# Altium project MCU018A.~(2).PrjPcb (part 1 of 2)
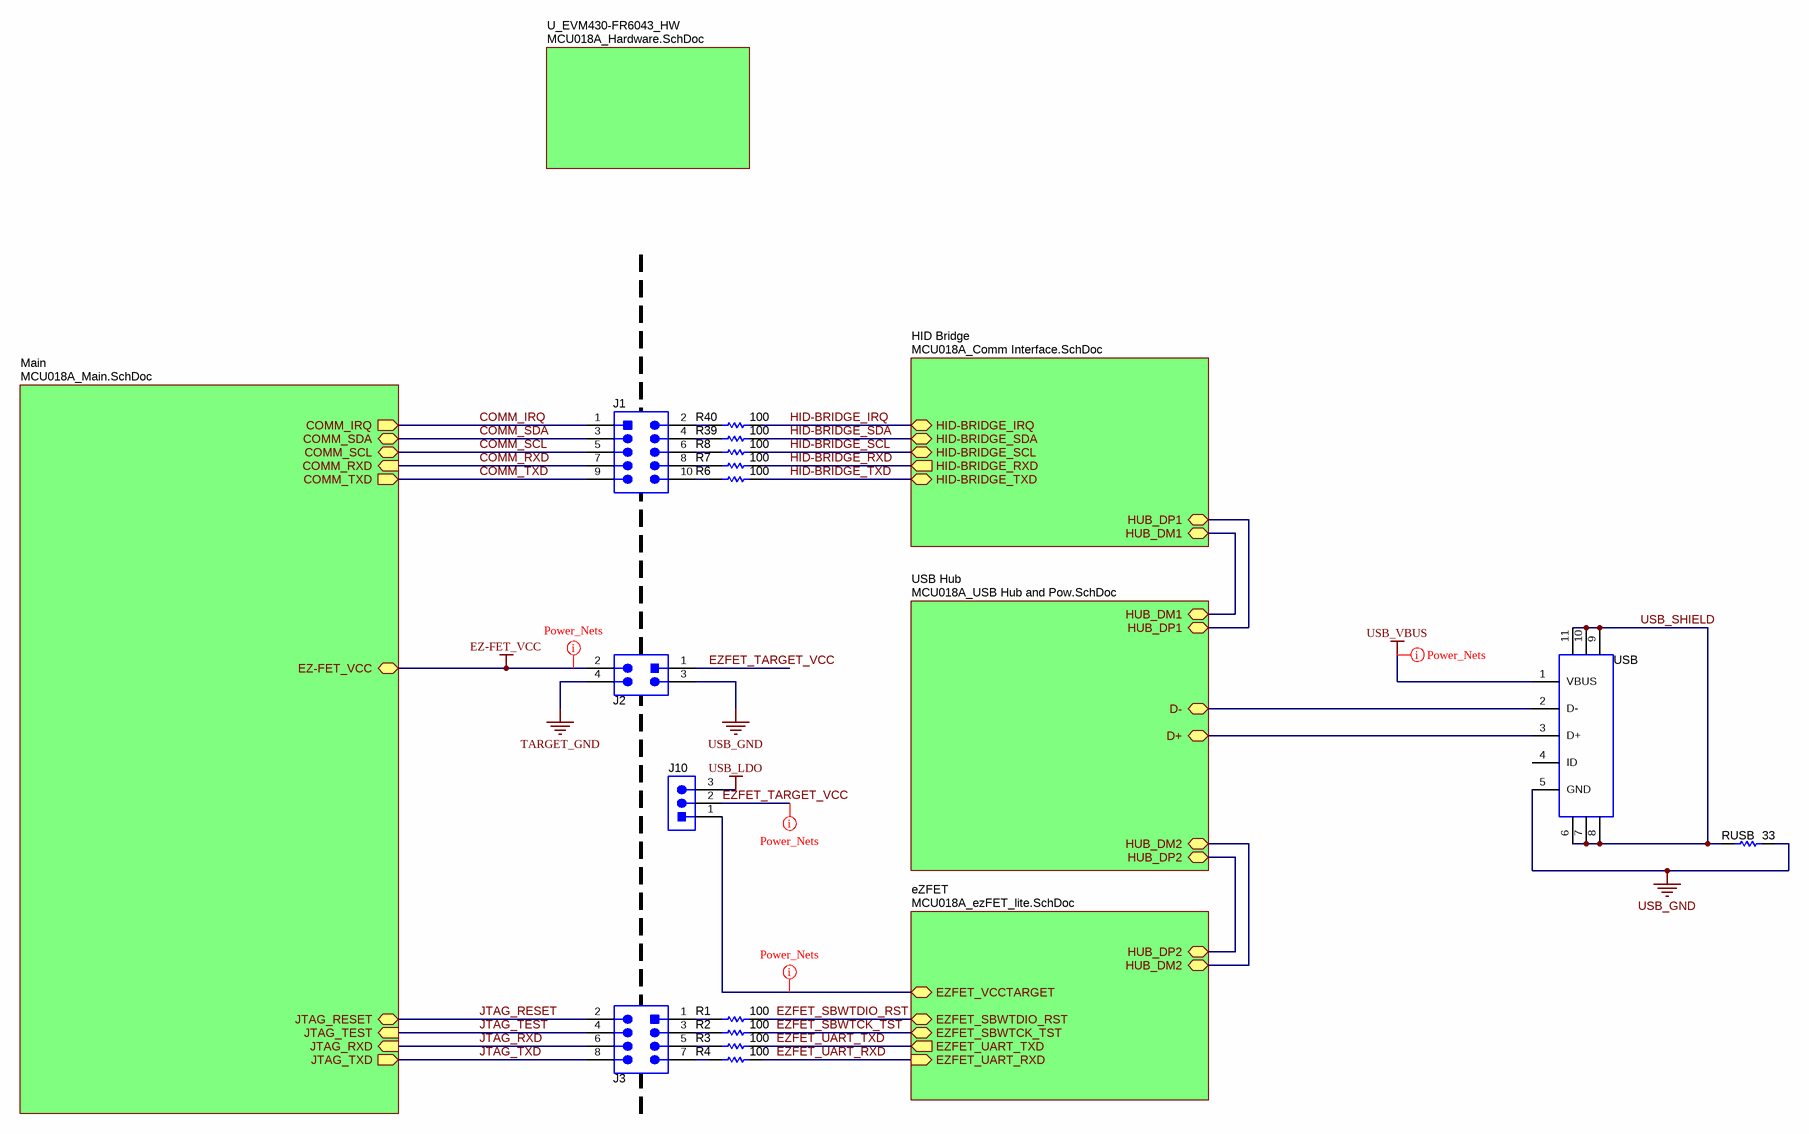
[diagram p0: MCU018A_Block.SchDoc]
TechSupport: http://www.ti.com/support; SCH_Rev: A; PRJ_Title: EVM430-FR6047; PRJ_Number: MCU018; PRJ_Engineer: Eddie LaCost; PRJ_Customer: Public Release; PCB_Rev: A; PCB_Layout: Eddie LaCost; Orderable: EVM430-FR6047; CopyrightYear: 2016
6 sheets, 270 parts. Net scope: hierarchical (ports join the sheet entries above them; power ports are global).
Board file: MCU018A.PcbDoc
Sheets:
  MCU018A_Block.SchDoc
    USB Hub = MCU018A_USB Hub and Pow.SchDoc
    U_EVM430-FR6043_HW = MCU018A_Hardware.SchDoc
    HID Bridge = MCU018A_Comm Interface.SchDoc
    eZFET = MCU018A_ezFET_lite.SchDoc
    Main = MCU018A_Main.SchDoc

## Sheet MCU018A_Block.SchDoc
size 431 x 279 mm; Date: Not shown in title block; ApprovedBy: Not shown in title block; CheckedBy: Not shown in title block; Author: Not shown in title block; CompanyName: Not shown in title block; Engineer: Not shown in title block; Organization: Not shown in title block; Address1: Not shown in title block; Address2: Not shown in title block; Address3: Not shown in title block; Address4: Not shown in title block; DocumentNumber: 1; Revision: Use project parameter SCH_Rev; SheetNumber: 1; SheetTotal: 6; PageSetup: Record=PageOptions¦CenterHorizontal=True¦CenterVertical=True¦PrintScale=1.00¦XCorrection=1.00¦YCorrection=1.00¦PrintKind=0¦BorderSize=5000000¦LeftOffset=0¦BottomOffset=0¦Orientation=2¦PaperLength=1000¦PaperWidth=1000¦Scale=100¦PaperSource=15¦PrintQuality=600¦MediaType=1¦DitherType=10¦PaperKind=Letter¦PrintScaleMode=1

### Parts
J1  61301021121  [WURTH_61301021121]  (value not drawn)
J2  PBC02DAAN  [Sullins_PxC02DAAN]  (value not drawn)
J3  PEC04DAAN  [CONN_PEC04DAAN]  (value not drawn)
J10  61300311121  [WURTH_61300311121]  (value not drawn)
R1  ValueDisplayed: 100  [0402S]  (hidden comment: CRCW0402100RJNED)
R2  ValueDisplayed: 100  [0402S]  (hidden comment: CRCW0402100RJNED)
R3  ValueDisplayed: 100  [0402S]  (hidden comment: CRCW0402100RJNED)
R4  ValueDisplayed: 100  [0402S]  (hidden comment: CRCW0402100RJNED)
R6  ValueDisplayed: 100  [0402S]  (hidden comment: CRCW0402100RJNED)
R7  ValueDisplayed: 100  [0402S]  (hidden comment: CRCW0402100RJNED)
R8  ValueDisplayed: 100  [0402S]  (hidden comment: CRCW0402100RJNED)
R39  ValueDisplayed: 100  [0402S]  (hidden comment: CRCW0402100RJNED)
R40  ValueDisplayed: 100  [0402S]  (hidden comment: CRCW0402100RJNED)
RUSB  value 33  [0402S]  (hidden comment: CRCW040233R0JNED)
USB  1051640001  [Molex_1051640001]  (value not drawn)

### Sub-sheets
eZFET = MCU018A_ezFET_lite.SchDoc: EZFET_VCCTARGET, EZFET_SBWTDIO_RST, EZFET_SBWTCK_TST, EZFET_UART_TXD, EZFET_UART_RXD, HUB_DP2, HUB_DM2
HID Bridge = MCU018A_Comm Interface.SchDoc: HID-BRIDGE_TXD, HID-BRIDGE_RXD, HID-BRIDGE_SCL, HID-BRIDGE_SDA, HID-BRIDGE_IRQ, HUB_DM1, HUB_DP1
Main = MCU018A_Main.SchDoc: COMM_IRQ, COMM_SDA, COMM_SCL, COMM_RXD, COMM_TXD, EZ-FET_VCC, JTAG_RESET, JTAG_TEST, JTAG_RXD, JTAG_TXD
U_EVM430-FR6043_HW = MCU018A_Hardware.SchDoc: no entries
USB Hub = MCU018A_USB Hub and Pow.SchDoc: HUB_DM1, HUB_DP1, D-, D+, HUB_DM2, HUB_DP2

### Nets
EZ-FET_VCC: J2.2 ; sheet Main/EZ-FET_VCC  [project net EZFET_VCC]
TARGET_GND: J2.4
USB_GND: J2.3 RUSB.1 USB.5(GND)
USB_LDO: J10.3
USB_VBUS: USB.1(VBUS)
COMM_IRQ: J1.1 ; sheet Main/COMM_IRQ
COMM_RXD: J1.7 ; sheet Main/COMM_RXD
COMM_SCL: J1.5 ; sheet Main/COMM_SCL
COMM_SDA: J1.3 ; sheet Main/COMM_SDA
COMM_TXD: J1.9 ; sheet Main/COMM_TXD
D+: USB.3(D+) ; sheet USB Hub/D+
D-: USB.2(D-) ; sheet USB Hub/D-
EZFET_SBWTCK_TST: R2.1 ; sheet eZFET/EZFET_SBWTCK_TST
EZFET_SBWTDIO_RST: R1.1 ; sheet eZFET/EZFET_SBWTDIO_RST
EZFET_TARGET_VCC: J2.1 J10.2
EZFET_UART_RXD: R4.1 ; sheet eZFET/EZFET_UART_RXD
EZFET_UART_TXD: R3.1 ; sheet eZFET/EZFET_UART_TXD
EZFET_VCCTARGET: J10.1 ; sheet eZFET/EZFET_VCCTARGET
HID-BRIDGE_IRQ: R40.1 ; sheet HID Bridge/HID-BRIDGE_IRQ
HID-BRIDGE_RXD: R7.1 ; sheet HID Bridge/HID-BRIDGE_RXD
HID-BRIDGE_SCL: R8.1 ; sheet HID Bridge/HID-BRIDGE_SCL
HID-BRIDGE_SDA: R39.1 ; sheet HID Bridge/HID-BRIDGE_SDA
HID-BRIDGE_TXD: R6.1 ; sheet HID Bridge/HID-BRIDGE_TXD
HUB_DM1: sheet USB Hub/HUB_DM1, sheet HID Bridge/HUB_DM1
HUB_DM2: sheet USB Hub/HUB_DM2, sheet eZFET/HUB_DM2
HUB_DP1: sheet USB Hub/HUB_DP1, sheet HID Bridge/HUB_DP1
HUB_DP2: sheet USB Hub/HUB_DP2, sheet eZFET/HUB_DP2
JTAG_RESET: J3.2 ; sheet Main/JTAG_RESET
JTAG_RXD: J3.6 ; sheet Main/JTAG_RXD
JTAG_TEST: J3.4 ; sheet Main/JTAG_TEST
JTAG_TXD: J3.8 ; sheet Main/JTAG_TXD
USB_SHIELD: RUSB.2 USB.6 USB.7 USB.8 USB.9 USB.10 USB.11
NetJ1_2: J1.2 R40.2
NetJ1_4: J1.4 R39.2
NetJ1_6: J1.6 R8.2
NetJ1_8: J1.8 R7.2
NetJ1_10: J1.10 R6.2
NetJ3_1: J3.1 R1.2
NetJ3_3: J3.3 R2.2
NetJ3_5: J3.5 R3.2
NetJ3_7: J3.7 R4.2

Not connected (* = marked no-connect by the designer): USB 4(ID)

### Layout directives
net class Power_Nets: EZFET_TARGET_VCC, EZFET_VCC, EZFET_VCCTARGET, USB_VBUS

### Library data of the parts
J1 = 61301021121: Header, 2.54 mm, 5x2, Gold, TH; Manufacturer: Wurth Elektronik; SymbolCreator: a0412235; Green_Lifecycle: Active; Green_REACh: Passed
J2 = PBC02DAAN: Header, 2.54mm, 2x2, Gold, TH; Manufacturer: Sullins Connector Solutions; SymbolCreator: a0412235; Pitch_mm: 2.54; Gender: Male; Shrouded: N; Row_Count: 2; Current_A: 3; Voltage_V: 1800; Cert_UL: Y
J3 = PEC04DAAN: Header, 100mil, 4x2, Tin, TH; Manufacturer: Sullins Connector Solutions; SymbolCreator: a0411947; Pitch_mm: 2.54; Gender: Male; Shrouded: N; Row_Count: 2; Current_A: 3; Voltage_V: 1800; Cert_UL: Y; Green_Lifecycle: Not Set; Green_REACh: Incomplete
J10 = 61300311121: Header, 2.54 mm, 3x1, Gold, TH; Manufacturer: Wurth Elektronik; SymbolCreator: a0799628; Green_Lifecycle: Active; Green_REACh: Passed
R1-R4 R6-R8 R39 R40 = CRCW0402100RJNED: RES, 100, 5%, 0.063 W, 0402; Manufacturer: Vishay-Dale; CompType: Resistor; Value: 100; Value_Code: 100R; Tolerance_%: 5; Power_W: 0.063; Value2: 0.063W; VDC_V: 50; TempCo: 200 ppm/C; EIA_Code: E24; U/M: EA; AEC Category: Q200
RUSB = CRCW040233R0JNED: RES, 33 ohm, 5%, 0.063W, 0402; Manufacturer: Vishay-Dale; CompType: Resistor; Value_Code: 33R0; Tolerance_%: 5; Power_W: 0.063; VDC_V: 50; TempCo: 200 ppm/C; EIA_Code: E24; U/M: EA
USB = 1051640001: Receptacle, USB 2.0, Micro B, 5 Position, R/A, SMT; Manufacturer: Molex; SymbolCreator: a0411947; Pitch_mm: 0.65; Gender: Female; ContactFinish: Gold; Current_A: 1.8; Voltage_V: 30; Cert_UL: Y

## Sheet MCU018A_USB Hub and Pow.SchDoc
size 431 x 279 mm; Date: Not shown in title block; ApprovedBy: Not shown in title block; CheckedBy: Not shown in title block; Author: Not shown in title block; CompanyName: Not shown in title block; Engineer: Not shown in title block; Organization: Not shown in title block; Address1: Not shown in title block; Address2: Not shown in title block; Address3: Not shown in title block; Address4: Not shown in title block; DocumentNumber: 3; Revision: Use project parameter SCH_Rev; SheetNumber: 3; SheetTotal: 6; PageSetup: Record=PageOptions¦CenterHorizontal=True¦CenterVertical=True¦PrintScale=1.00¦XCorrection=1.00¦YCorrection=1.00¦PrintKind=0¦BorderSize=5000000¦LeftOffset=0¦BottomOffset=0¦Orientation=2¦PaperLength=1000¦PaperWidth=1000¦Scale=100¦PaperSource=15¦PrintQuality=600¦MediaType=1¦DitherType=10¦PaperKind=Letter¦PrintScaleMode=1
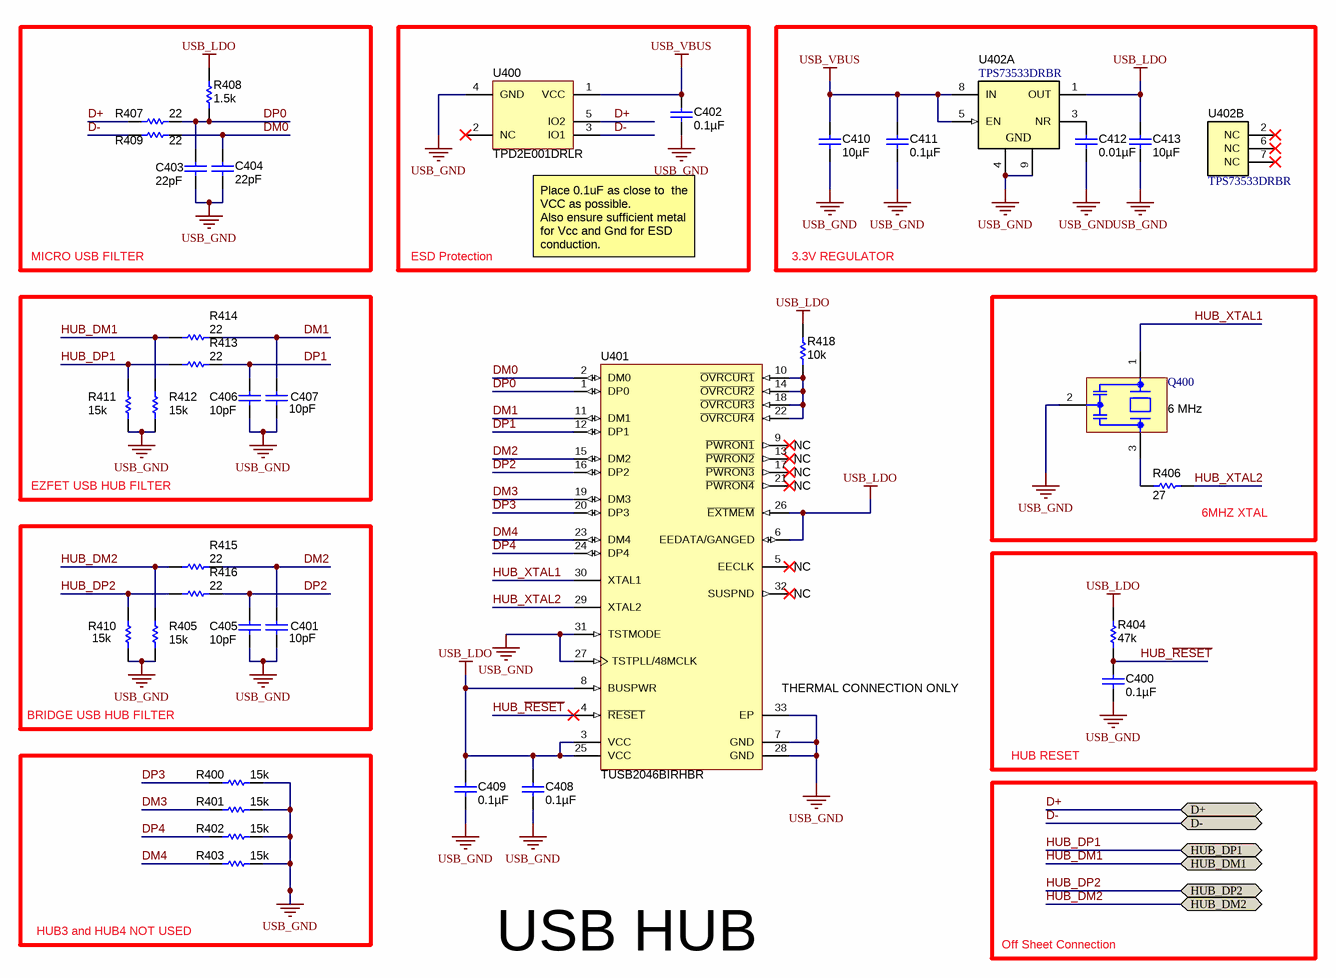
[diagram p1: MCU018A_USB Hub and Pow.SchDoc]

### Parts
C400  ValueDisplayed: 0.1µF  [0402S]  (hidden comment: GRM155R71C104KA88D)
C401  ValueDisplayed: 10pF  [0402S]  (hidden comment: GRM1555C1H100JA01D)
C402  ValueDisplayed: 0.1µF  [0402S]  (hidden comment: GRM155R71C104KA88D)
C403  ValueDisplayed: 22pF  [0402S]  (hidden comment: GRM1555C1H220JA01D)
C404  ValueDisplayed: 22pF  [0402S]  (hidden comment: GRM1555C1H220JA01D)
C405  ValueDisplayed: 10pF  [0402S]  (hidden comment: GRM1555C1H100JA01D)
C406  ValueDisplayed: 10pF  [0402S]  (hidden comment: GRM1555C1H100JA01D)
C407  ValueDisplayed: 10pF  [0402S]  (hidden comment: GRM1555C1H100JA01D)
C408  ValueDisplayed: 0.1µF  [0402S]  (hidden comment: GRM155R71C104KA88D)
C409  ValueDisplayed: 0.1µF  [0402S]  (hidden comment: GRM155R71C104KA88D)
C410  ValueDisplayed: 10µF  [0603S]  (hidden comment: GRM188R61A106ME69D)
C411  ValueDisplayed: 0.1µF  [0402S]  (hidden comment: GRM155R71C104KA88D)
C412  ValueDisplayed: 0.01µF  [0402S]  (hidden comment: GRM155R71C103KA01D)
C413  ValueDisplayed: 10µF  [0603S]  (hidden comment: GRM188R61A106ME69D)
Q400  Frequency: 6 MHz  [Murata_CSTCR]  (hidden comment: CSTCR6M00G53Z-R0)
R400  ValueDisplayed: 15k  [0402S]  (hidden comment: CRCW040215K0JNED)
R401  ValueDisplayed: 15k  [0402S]  (hidden comment: CRCW040215K0JNED)
R402  ValueDisplayed: 15k  [0402S]  (hidden comment: CRCW040215K0JNED)
R403  ValueDisplayed: 15k  [0402S]  (hidden comment: CRCW040215K0JNED)
R404  value 47k  [0402S]  (hidden comment: CRCW040247K0JNED)
R405  ValueDisplayed: 15k  [0402S]  (hidden comment: CRCW040215K0JNED)
R406  value 27  [0402S]  (hidden comment: CRCW040227R0JNED)
R407  value 22  [0402S]  (hidden comment: CRCW040222R0JNED)
R408  value 1.5k  [0402S]  (hidden comment: CRCW04021K50JNED)
R409  value 22  [0402S]  (hidden comment: CRCW040222R0JNED)
R410  ValueDisplayed: 15k  [0402S]  (hidden comment: CRCW040215K0JNED)
R411  ValueDisplayed: 15k  [0402S]  (hidden comment: CRCW040215K0JNED)
R412  ValueDisplayed: 15k  [0402S]  (hidden comment: CRCW040215K0JNED)
R413  value 22  [0402S]  (hidden comment: CRCW040222R0JNED)
R414  value 22  [0402S]  (hidden comment: CRCW040222R0JNED)
R415  value 22  [0402S]  (hidden comment: CRCW040222R0JNED)
R416  value 22  [0402S]  (hidden comment: CRCW040222R0JNED)
R418  ValueDisplayed: 10k  [0402S]  (hidden comment: CRCW040210K0JNED)
U400  TPD2E001DRLR  [DRL0005A]
U401  TUSB2046BIRHBR  [RHB0032E]
U402  TPS73533DRBR  [DRB0008A]  (parts A,B of 2)

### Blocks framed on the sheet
MICRO USB FILTER: C403 C404 R407-R409
ESD Protection: C402 U400
3.3V REGULATOR: C410-C413 U402
EZFET USB HUB FILTER: C406 C407 R411-R414
6MHZ XTAL: Q400 R406
BRIDGE USB HUB FILTER: C401 C405 R405 R410 R415 R416
HUB RESET: C400 R404
HUB3 and HUB4 NOT USED: R400-R403

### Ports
D+ (bidir), D- (bidir), HUB_DM1 (bidir), HUB_DM2 (bidir), HUB_DP1 (bidir), HUB_DP2 (bidir)

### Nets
USB_GND: C400.2 C401.2 C402.2 C403.2 C404.2 C405.2 C406.2 C407.2 C408.2 C409.2 C410.2 C411.2 C412.2 C413.2 Q400.2(GND) R400.1 R401.2 R402.2 R403.2 R405.1 R410.1 R411.1 R412.1 U400.4(GND) U401.7(GND) U401.27(TSTPLL/48MCLK) U401.28(GND) U401.31(TSTMODE) U401.33(EP) U402.4(GND) U402.9(GND)
USB_LDO: C408.1 C409.1 C413.1 R404.2 R408.2 R418.2 U401.3(VCC) U401.6(EEDATA/GANGED) U401.8(BUSPWR) U401.25(VCC) U401.26(~{EXTMEM}) U402.1(OUT)
USB_VBUS: C402.1 C410.1 C411.1 U400.1(VCC) U402.5(EN) U402.8(IN)
D+: R407.1 U400.5(IO2) ; port D+
D-: R409.1 U400.3(IO1) ; port D-
DM0: C404.1 R409.2 U401.2(DM0)
DM1: C407.1 R414.2 U401.11(DM1)
DM2: C401.1 R415.2 U401.15(DM2)
DM3: R401.1 U401.19(DM3)
DM4: R403.1 U401.23(DM4)
DP0: C403.1 R407.2 R408.1 U401.1(DP0)
DP1: C406.1 R413.2 U401.12(DP1)
DP2: C405.1 R416.2 U401.16(DP2)
DP3: R400.2 U401.20(DP3)
DP4: R402.1 U401.24(DP4)
HUB_DM1: R412.2 R414.1 ; port HUB_DM1
HUB_DM2: R405.2 R415.1 ; port HUB_DM2
HUB_DP1: R411.2 R413.1 ; port HUB_DP1
HUB_DP2: R410.2 R416.1 ; port HUB_DP2
HUB_~{RESET}: C400.1 R404.1 U401.4(~{RESET})
HUB_XTAL1: Q400.1(In) U401.30(XTAL1)
HUB_XTAL2: R406.2 U401.29(XTAL2)
NetC412_1: C412.1 U402.3(NR)
NetQ400_3: Q400.3(Out) R406.1
NetR418_1: R418.1 U401.10(~{OVRCUR1}) U401.14(~{OVRCUR2}) U401.18(~{OVRCUR3}) U401.22(~{OVRCUR4})

Not connected (* = marked no-connect by the designer): U400 2(NC)*; U401 5(EECLK)* 9(~{PWRON1})* 13(~{PWRON2})* 17(~{PWRON3})* 21(~{PWRON4})* 32(SUSPND)*; U402 2(NC)* 6(NC)* 7(NC)*

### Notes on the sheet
- Place 0.1uF as close to  the VCC as possible.
  Also ensure sufficient metal for Vcc and Gnd for ESD conduction.
- (near U401) NC
- (near U401) THERMAL CONNECTION ONLY
- USB HUB
- Off Sheet Connection

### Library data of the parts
C400 C402 C411 = GRM155R71C104KA88D: CAP, CERM, 0.1 µF, 16 V, +/- 10%, X7R, 0402; Manufacturer: MuRata; Polarized: N; CompType: Capacitor; Value: 0.1uF; U/M: EA; Cap_F: 0.0000001; Tolerance_%: 10; Value1: Unknown; VDC_V: 16; Value2: 16V; TaMin_C: -55; TaMax_C: 125; Cap_Case: 0402; AEC Category: Q200
C401 C405-C407 = GRM1555C1H100JA01D: CAP, CERM, 10 pF, 50 V, +/- 5%, C0G/NP0, 0402; Manufacturer: MuRata; Polarized: N; CompType: Capacitor; Value: 10pF; U/M: EA; Cap_F: 0.00000000001; Tolerance_%: 5; Value1: Unknown; VDC_V: 50; Value2: 50V; TaMin_C: -55; TaMax_C: 125; Cap_Case: 0402
C403 C404 = GRM1555C1H220JA01D: CAP, CERM, 22 pF, 50 V, +/- 5%, C0G/NP0, 0402; Manufacturer: MuRata; Polarized: N; CompType: Capacitor; Value: 22pF; U/M: EA; Cap_F: 0.000000000022; Tolerance_%: 5; Value1: Unknown; VDC_V: 50; Value2: 50V; TaMin_C: -55; TaMax_C: 125; Cap_Case: 0402
C408 C409 = GRM155R71C104KA88D: CAP, CERM, 0.1 µF, 16 V, +/- 10%, X7R, 0402; Manufacturer: MuRata; Polarized: N; CompType: Capacitor; Value: 0.1uF; U/M: EA; Cap_F: 0.0000001; Tolerance_%: 10; Value1: Unknown; VDC_V: 16; Value2: 16V; TaMin_C: -55; TaMax_C: 125; Cap_Case: 0402
C410 C413 = GRM188R61A106ME69D: CAP, CERM, 10 µF, 10 V, +/- 20%, X5R, 0603; Manufacturer: MuRata; Polarized: N; CompType: Capacitor; Value: 10uF; U/M: EA; Cap_F: 0.00001; Tolerance_%: 20; Value1: Unknown; VDC_V: 10; Value2: 10V; TaMin_C: -55; TaMax_C: 85; Cap_Case: 0603; AEC Category: Q200; SizeArea_mm2: 1.28; SizeAreaWB_mm2: 4.68; SizeX_mm: 1.6; SizeY_mm: 0.8; SizeZ_mm: 1
C412 = GRM155R71C103KA01D: CAP, CERM, 0.01 µF, 16 V, +/- 10%, X7R, 0402; Manufacturer: MuRata; Polarized: N; CompType: Capacitor; Value: 0.01uF; U/M: EA; Cap_F: 0.00000001; Tolerance_%: 10; Value1: Unknown; VDC_V: 16; Value2: 16V; TaMin_C: -55; TaMax_C: 125; Cap_Case: 0402; AEC Category: Q200; SizeArea_mm2: 0.5; SizeAreaWB_mm2: 3; SizeX_mm: 1; SizeZ_mm: 0.6
Q400 = CSTCR6M00G53Z-R0: Resonator, 6MHz, 15pF SMD; Manufacturer: MuRata; SymbolCreator: a0799721; U/M: EA; TaMin_C: -40; TaMax_C: 125; Frequency Stability: ±0.2 %
R400 R410 = CMP-0026842-3: RES, 15 k, 5%, 0.063 W, AEC-Q200 Grade 0, 0402; Manufacturer: Vishay-Dale; Power_W: 63mW; TempCo: 200 ppm/C; Value_Code: 15k0; Value: 15k; EIA_Code: E24; SizeX_mm: 1; SizeY_mm: 0.5; SizeZ_mm: 0.6; Value2: 0.063W; CompType: Resistor; AEC Qualified: Y; VDC_V: 50V; AEC Category: Q200; AEC Grade: 0
R401-R403 R405 R411 R412 = CRCW040215K0JNED: RES, 15 k, 5%, 0.063 W, 0402; Manufacturer: Vishay-Dale; CompType: Resistor; Value: 15k; Res_ohm: 15000; Value_Code: 15k0; Tolerance_%: 5; Power_W: 0.063; Value2: 0.063W; VDC_V: 50; TempCo: 200 ppm/C; EIA_Code: E24; U/M: EA
R404 = CRCW040247K0JNED: RES, 47 k, 5%, 0.063 W, 0402; Manufacturer: Vishay-Dale; CompType: Resistor; Res_ohm: 47000; Value_Code: 47k0; Tolerance_%: 5; Power_W: 0.063; Value2: 0.063W; VDC_V: 50; TempCo: 200 ppm/C; EIA_Code: E24; U/M: EA
R406 = CRCW040227R0JNED: RES, 27 ohm, 5%, 0.063W, 0402; Manufacturer: Vishay-Dale; CompType: Resistor; Value_Code: 27R0; Tolerance_%: 5; Power_W: 0.063; VDC_V: 50; TempCo: 200 ppm/C; EIA_Code: E24; U/M: EA
R407 R409 R413-R416 = CRCW040222R0JNED: RES, 22 ohm, 5%, 0.063W, 0402; Manufacturer: Vishay-Dale; CompType: Resistor; Value_Code: 22R0; Tolerance_%: 5; Power_W: 0.063; VDC_V: 50; TempCo: 200 ppm/C; EIA_Code: E24; U/M: EA
R408 = CRCW04021K50JNED: RES, 1.5 k, 5%, 0.063 W, 0402; Manufacturer: Vishay-Dale; CompType: Resistor; Res_ohm: 1500; Value_Code: 1k50; Tolerance_%: 5; Power_W: 0.063; Value2: 0.063W; VDC_V: 50; TempCo: 200 ppm/C; EIA_Code: E24; U/M: EA
R418 = CRCW040210K0JNED: RES, 10 k, 5%, 0.063 W, 0402; Manufacturer: Vishay-Dale; CompType: Resistor; Value: 10k; Res_ohm: 10000; Value_Code: 10k0; Tolerance_%: 5; Power_W: 0.063; Value2: 0.063W; VDC_V: 50; TempCo: 200 ppm/C; EIA_Code: E24; U/M: EA; AEC Category: Q200
U400 = TPD2E001DRLR: Low-Capacitance + / - 15 kV ESD-Protection Array for High-Speed Data Interfaces, 2 Channels, -40 to +85 degC, 5-pin SOT (DRL), Green (RoHS & no Sb/Br); Manufacturer: Texas Instruments; Alternate Manufacturer: None; Alternate PartNumber: Equivalent; Breakdown Voltage(Min)(V): 11; IEC 61000-4-2 Air-Gap(+/- kV): 15; IEC 61000-4-2 Contact(+/- kV): 8; IO Capacitance(Typ)(pF): 1.5; IO Leakage Current(nA): 1; SubFamily: ESD Solution; USB High Speed: TRUE
U401 = TUSB2046BIRHBR: 4-Port Full-Speed USB Hub, 3.3V, -40 to 85 degC, 32-Pin QFN (RHB), Green (RoHS & no Sb/Br); Manufacturer: Texas Instruments; Alternate Manufacturer: None; Alternate PartNumber: Equivalent; SubFamily: USB Hub Controller; USB Speed: Full; USB Full Speed: True; Supply Voltage(s)(V): 3.3
U402 = TPS73533DRBR: Single Output High PSRR LDO, 500 mA, Fixed 3.3 V Output, 2.7 to 6.5 V Input, with Low IQ, 8-pin SON (DRB), -40 to 125 degC, Green (RoHS & no Sb/Br); Manufacturer: Texas Instruments; Alternate PartNumber: Equivalent; Accuracy(%): 2; Fixed Output Options(V): 3.3; Iout(Max)(A): 0.5; Iq(Typ)(mA): 0.04; SubFamily: Single Channel LDO; Vdo(Typ)(mV): 280; Vin(Max)(V): 6.5; Vin(Min)(V): 2.7

## Sheet MCU018A_Hardware.SchDoc
size 431 x 279 mm; Date: Not shown in title block; ApprovedBy: Not shown in title block; CheckedBy: Not shown in title block; Author: Not shown in title block; CompanyName: Not shown in title block; Engineer: Not shown in title block; Organization: Not shown in title block; Address1: Not shown in title block; Address2: Not shown in title block; Address3: Not shown in title block; Address4: Not shown in title block; DocumentNumber: 6; Revision: Use project parameter SCH_Rev; SheetNumber: 6; SheetTotal: 6; PageSetup: Record=PageOptions¦CenterHorizontal=True¦CenterVertical=True¦PrintScale=1.00¦XCorrection=1.00¦YCorrection=1.00¦PrintKind=0¦BorderSize=5000000¦LeftOffset=0¦BottomOffset=0¦Orientation=2¦PaperLength=1000¦PaperWidth=1000¦Scale=100¦PaperSource=15¦PrintQuality=600¦MediaType=1¦DitherType=10¦PaperKind=Letter¦PrintScaleMode=1
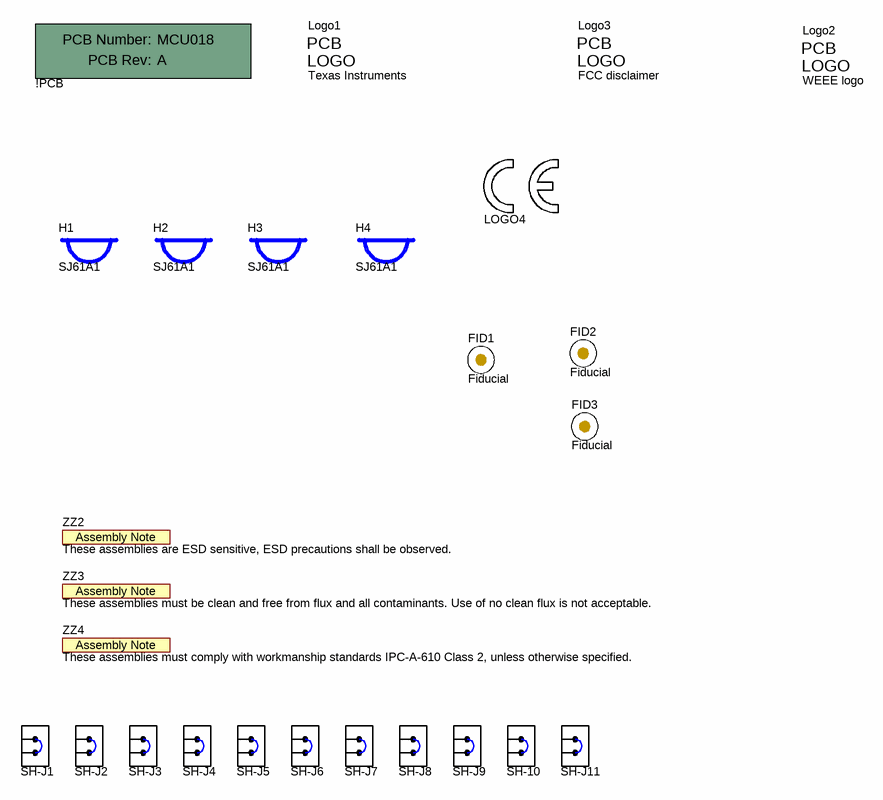
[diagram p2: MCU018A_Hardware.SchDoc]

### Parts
!PCB  Printed Circuit Board  (value not drawn)  (mechanical)
FID1  Fiducial  [Fiducial10-30]
FID2  Fiducial  [Fiducial10-30]
FID3  Fiducial  [Fiducial10-30]
H1  SJ61A1  [Bumpon_SJ61A1]
H2  SJ61A1  [Bumpon_SJ61A1]
H3  SJ61A1  [Bumpon_SJ61A1]
H4  SJ61A1  [Bumpon_SJ61A1]
Logo1  Texas Instruments  [TI_Stacked_Overlay_Small]  (no BOM)
Logo2  WEEE logo  [WEEE_Minimum]  (no BOM)
Logo3  FCC disclaimer  [FCC_disclaimer]  (no BOM)
LOGO4  CE Mark  [CE_Mark_5mm]  (value not drawn)  (no BOM)
SH-10  60900213421  [Wurth_60900213421]  (value not drawn)
SH-J1  60900213421  [Wurth_60900213421]  (value not drawn)
SH-J2  60900213421  [Wurth_60900213421]  (value not drawn)
SH-J3  60900213421  [Wurth_60900213421]  (value not drawn)
SH-J4  60900213421  [Wurth_60900213421]  (value not drawn)
SH-J5  60900213421  [Wurth_60900213421]  (value not drawn)
SH-J6  60900213421  [Wurth_60900213421]  (value not drawn)
SH-J7  60900213421  [Wurth_60900213421]  (value not drawn)
SH-J8  60900213421  [Wurth_60900213421]  (value not drawn)
SH-J9  60900213421  [Wurth_60900213421]  (value not drawn)
SH-J11  60900213421  [Wurth_60900213421]  (value not drawn)
ZZ2  These assemblies are ESD sensitive, ESD precautions shall be observed.  [AssemblyNote]  (no BOM)
ZZ3  These assemblies must be clean and free from flux and all contaminants. Use of no clean flux is not acceptable.  [AssemblyNote]  (no BOM)
ZZ4  These assemblies must comply with workmanship standards IPC-A-610 Class 2, unless otherwise specified.  [AssemblyNote]  (no BOM)

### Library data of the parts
!PCB = PCB: Manufacturer: Any; PartNumber: MCU018; SymbolCreator: a0412235
FID1-FID3 = CMP-0077181-1: Fiducial mark.  There is nothing to buy or mount.
H1-H4 = SJ61A1: Bumpon, Cylindrical, 0.312 X 0.200, Black; Manufacturer: 3M; SymbolCreator: a0412235; Green_Lifecycle: Not Set; Green_REACh: Incomplete
Logo1 = TI_Logo: Texas Instrument Corporate Signature; SymbolCreator: codlsc
Logo2 = CMP-0074769-1
Logo3 = FCC_disclaimer: SymbolCreator: codlsc
LOGO4 = CE Mark: SymbolCreator: a0412235
SH-10 SH-J1-SH-J9 SH-J11 = 60900213421: Shunt, 2.54mm, Gold, Black; Manufacturer: Wurth Elektronik
ZZ2-ZZ4 = AssemblyNote: SymbolCreator: codlsc

## Sheet MCU018A_Comm Interface.SchDoc
size 431 x 279 mm; Date: Not shown in title block; ApprovedBy: Not shown in title block; CheckedBy: Not shown in title block; Author: Not shown in title block; CompanyName: Not shown in title block; Engineer: Not shown in title block; Organization: Not shown in title block; Address1: Not shown in title block; Address2: Not shown in title block; Address3: Not shown in title block; Address4: Not shown in title block; DocumentNumber: 5; Revision: Use project parameter SCH_Rev; SheetNumber: 5; SheetTotal: 6; PageSetup: Record=PageOptions¦CenterHorizontal=True¦CenterVertical=True¦PrintScale=0.62¦XCorrection=1.00¦YCorrection=1.00¦PrintKind=0¦BorderSize=5000000¦LeftOffset=0¦BottomOffset=0¦Orientation=2¦PaperLength=1000¦PaperWidth=1000¦Scale=100¦PaperSource=15¦PrintQuality=600¦MediaType=1¦DitherType=10¦PaperKind=Letter¦PrintScaleMode=1
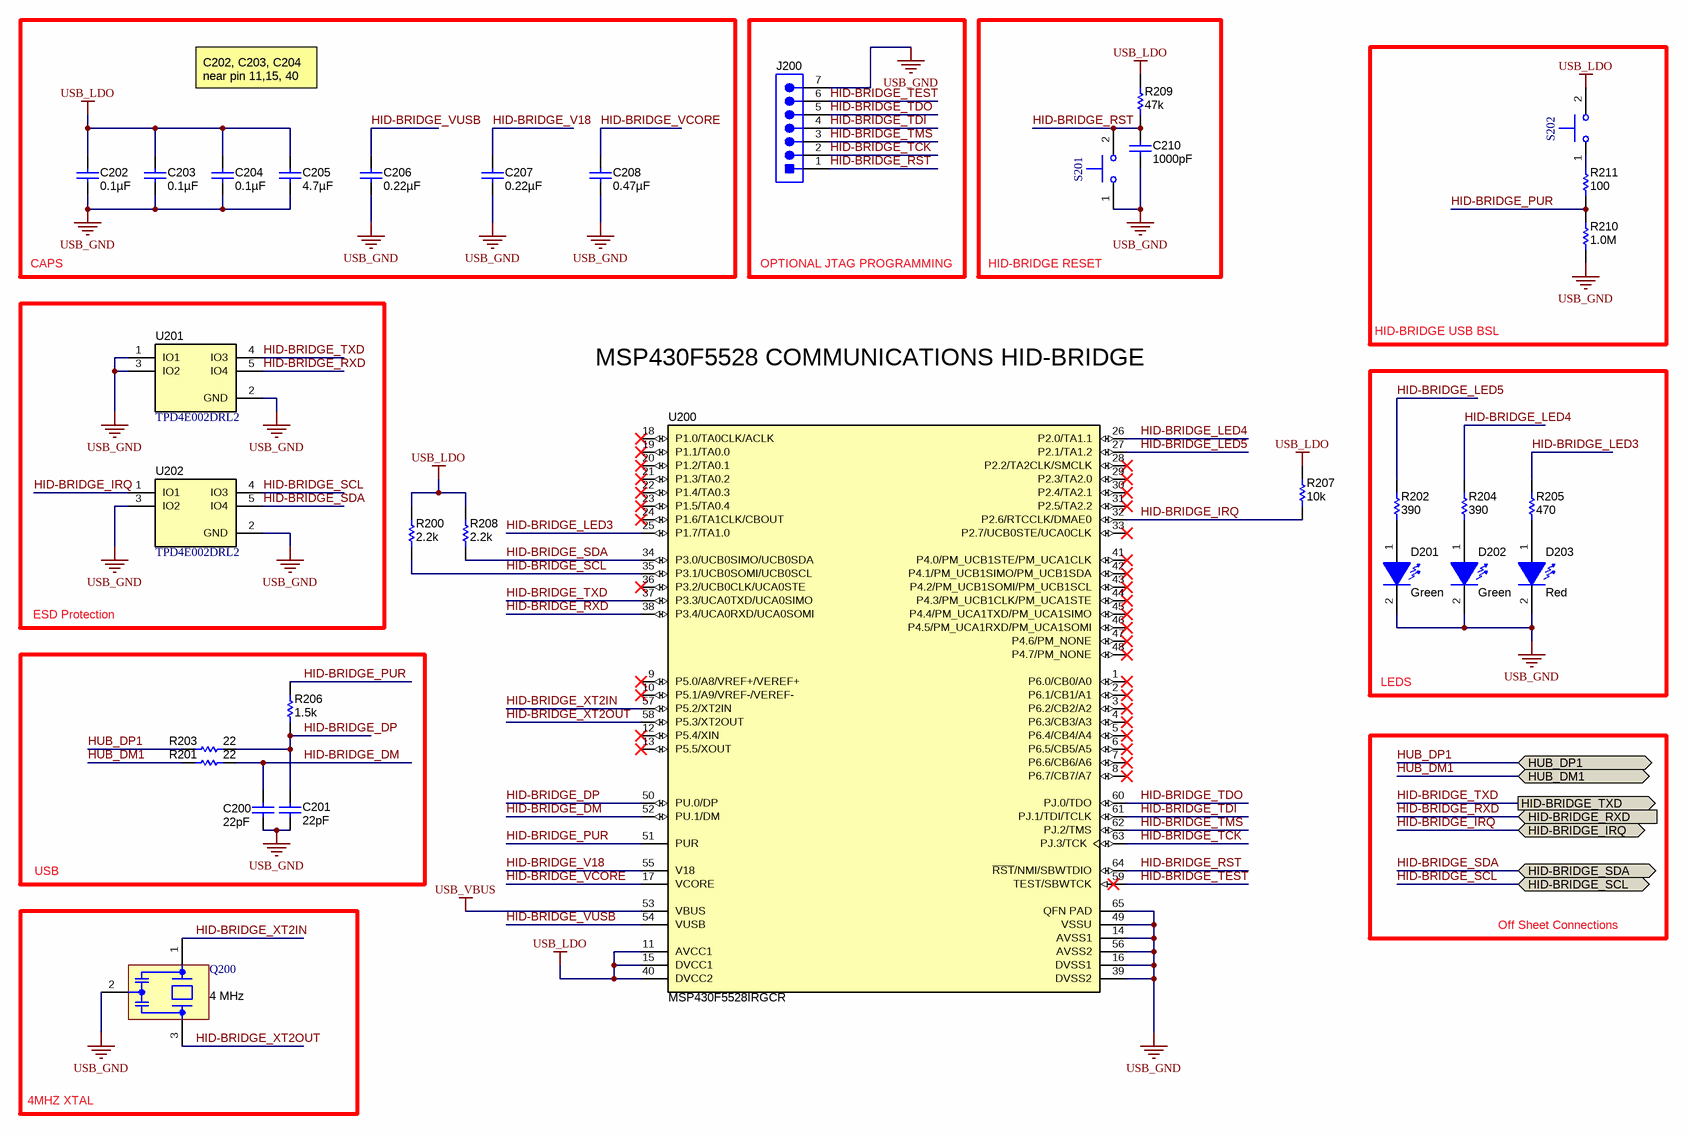
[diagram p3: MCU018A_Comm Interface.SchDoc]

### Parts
C200  ValueDisplayed: 22pF  [0402S]  (hidden comment: GRM1555C1H220JA01D)
C201  ValueDisplayed: 22pF  [0402S]  (hidden comment: GRM1555C1H220JA01D)
C202  ValueDisplayed: 0.1µF  [0402S]  (hidden comment: GRM155R71C104KA88D)
C203  ValueDisplayed: 0.1µF  [0402S]  (hidden comment: GRM155R71C104KA88D)
C204  ValueDisplayed: 0.1µF  [0402S]  (hidden comment: GRM155R71C104KA88D)
C205  ValueDisplayed: 4.7µF  [0603S]  (hidden comment: GRM188R61A475MAAJ)
C206  ValueDisplayed: 0.22µF  [0402S]  (hidden comment: GRM155R71C224KA12D)
C207  ValueDisplayed: 0.22µF  [0402S]  (hidden comment: GRM155R71C224KA12D)
C208  ValueDisplayed: 0.47µF  [0402S]  (hidden comment: GRM155R61C474KE01)
C210  ValueDisplayed: 1000pF  [0402S]  (hidden comment: GRM1555C1H102JA01D)
D201  value Green  [LTST-C191_Green]  (hidden comment: LTST-C191TGKT)
D202  value Green  [LTST-C191_Green]  (hidden comment: LTST-C191TGKT)
D203  value Red  [LED_LTST-C190_Red]  (hidden comment: LTST-C190CKT)
J200  PBC07SAAN  [Sullins_xxC07SAAN]  (value not drawn)
Q200  Frequency: 4 MHz  [Murata_CSTCR]  (hidden comment: CSTCR4M00G15L99-R0)
R200  ValueDisplayed: 2.2k  [0402S]  (hidden comment: CRCW04022K20JNED)
R201  ValueDisplayed: 22  [0402S]  (hidden comment: CRCW040222R0JNED)
R202  value 390  [0402S]  (hidden comment: CRCW0402390RJNED)
R203  ValueDisplayed: 22  [0402S]  (hidden comment: CRCW040222R0JNED)
R204  value 390  [0402S]  (hidden comment: CRCW0402390RJNED)
R205  ValueDisplayed: 470  [0402S]  (hidden comment: CRCW0402470RJNED)
R206  ValueDisplayed: 1.5k  [0402S]  (hidden comment: CRCW04021K50JNED)
R207  ValueDisplayed: 10k  [0402S]  (hidden comment: CRCW040210K0JNED)
R208  ValueDisplayed: 2.2k  [0402S]  (hidden comment: CRCW04022K20JNED)
R209  value 47k  [0402S]  (hidden comment: CRCW040247K0JNED)
R210  ValueDisplayed: 1.0M  [0402S]  (hidden comment: CRCW04021M00JNED)
R211  ValueDisplayed: 100  [0402S]  (hidden comment: CRCW0402100RJNED)
S201  B3U-1000P  [SW_B3U-1000P]  (value not drawn)
S202  B3U-1000P  [SW_B3U-1000P]  (value not drawn)
U200  MSP430F5528IRGCR  [RGC0064B]
U201  TPD4E002DRL2  [DRL0005A]
U202  TPD4E002DRL2  [DRL0005A]

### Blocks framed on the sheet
CAPS: C202-C208
OPTIONAL JTAG PROGRAMMING: J200
HID-BRIDGE RESET: C210 R209 S201
HID-BRIDGE USB BSL: R210 R211 S202
ESD Protection: U201 U202
LEDS: D201-D203 R202 R204 R205
USB: C200 C201 R201 R203 R206
4MHZ XTAL: Q200

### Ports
HID-BRIDGE_IRQ (bidir), HID-BRIDGE_RXD (in), HID-BRIDGE_SCL (bidir), HID-BRIDGE_SDA (bidir), HID-BRIDGE_TXD (out), HUB_DM1 (bidir), HUB_DP1 (bidir)

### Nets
USB_GND: C200.2 C201.2 C202.2 C203.2 C204.2 C205.2 C206.2 C207.2 C208.2 C210.2 D201.2(K) D202.2(K) D203.2(K) J200.7 Q200.2(GND) R210.1 S201.1 U200.14(AVSS1) U200.16(DVSS1) U200.39(DVSS2) U200.49(VSSU) U200.56(AVSS2) U200.65(QFN_PAD) U201.1(IO1) U201.2(GND) U201.3(IO2) U202.2(GND) U202.3(IO2)
USB_LDO: C202.1 C203.1 C204.1 C205.1 R200.2 R207.2 R208.2 R209.2 S202.2 U200.11(AVCC1) U200.15(DVCC1) U200.40(DVCC2)
USB_VBUS: U200.53(VBUS)
HID-BRIDGE_DM: C200.1 R201.2 U200.52(PU.1/DM)
HID-BRIDGE_DP: C201.1 R203.2 R206.1 U200.50(PU.0/DP)
HID-BRIDGE_IRQ: R207.1 U200.32(P2.6/RTCCLK/DMAE0) U202.1(IO1) ; port HID-BRIDGE_IRQ
HID-BRIDGE_LED3: R205.2 U200.25(P1.7/TA1.0)
HID-BRIDGE_LED4: R204.2 U200.26(P2.0/TA1.1)
HID-BRIDGE_LED5: R202.2 U200.27(P2.1/TA1.2)
HID-BRIDGE_PUR: R206.2 R210.2 R211.1 U200.51(PUR)
HID-BRIDGE_RST: C210.1 J200.1 R209.1 S201.2 U200.64(~{RST}/NMI/SBWTDIO)
HID-BRIDGE_RXD: U200.38(P3.4/UCA0RXD/UCA0SOMI) U201.5(IO4) ; port HID-BRIDGE_RXD
HID-BRIDGE_SCL: R200.1 U200.35(P3.1/UCB0SOMI/UCB0SCL) U202.4(IO3) ; port HID-BRIDGE_SCL
HID-BRIDGE_SDA: R208.1 U200.34(P3.0/UCB0SIMO/UCB0SDA) U202.5(IO4) ; port HID-BRIDGE_SDA
HID-BRIDGE_TCK: J200.2 U200.63(PJ.3/TCK)
HID-BRIDGE_TDI: J200.4 U200.61(PJ.1/TDI/TCLK)
HID-BRIDGE_TDO: J200.5 U200.60(PJ.0/TDO)
HID-BRIDGE_TEST: J200.6 U200.59(TEST/SBWTCK)
HID-BRIDGE_TMS: J200.3 U200.62(PJ.2/TMS)
HID-BRIDGE_TXD: U200.37(P3.3/UCA0TXD/UCA0SIMO) U201.4(IO3) ; port HID-BRIDGE_TXD
HID-BRIDGE_V18: C207.1 U200.55(V18)
HID-BRIDGE_VCORE: C208.1 U200.17(VCORE)
HID-BRIDGE_VUSB: C206.1 U200.54(VUSB)
HID-BRIDGE_XT2IN: Q200.1(In) U200.57(P5.2/XT2IN)
HID-BRIDGE_XT2OUT: Q200.3(Out) U200.58(P5.3/XT2OUT)
HUB_DM1: R201.1 ; port HUB_DM1
HUB_DP1: R203.1 ; port HUB_DP1
NetD201_1: D201.1(A) R202.1
NetD202_1: D202.1(A) R204.1
NetD203_1: D203.1(A) R205.1
NetR211_2: R211.2 S202.1

Not connected (* = marked no-connect by the designer): U200 1(P6.0/CB0/A0)* 2(P6.1/CB1/A1)* 3(P6.2/CB2/A2)* 4(P6.3/CB3/A3)* 5(P6.4/CB4/A4)* 6(P6.5/CB5/A5)* 7(P6.6/CB6/A6)* 8(P6.7/CB7/A7)* 9(P5.0/A8/VREF+/VEREF+)* 10(P5.1/A9/VREF-/VEREF-)* 12(P5.4/XIN)* 13(P5.5/XOUT)* 18(P1.0/TA0CLK/ACLK)* 19(P1.1/TA0.0)* 20(P1.2/TA0.1)* 21(P1.3/TA0.2)* 22(P1.4/TA0.3)* 23(P1.5/TA0.4)* 24(P1.6/TA1CLK/CBOUT)* 28(P2.2/TA2CLK/SMCLK)* 29(P2.3/TA2.0)* 30(P2.4/TA2.1)* 31(P2.5/TA2.2)* 33(P2.7/UCB0STE/UCA0CLK)* 36(P3.2/UCB0CLK/UCA0STE)* 41(P4.0/PM_UCB1STE/PM_UCA1CLK)* 42(P4.1/PM_UCB1SIMO/PM_UCB1SDA)* 43(P4.2/PM_UCB1SOMI/PM_UCB1SCL)* 44(P4.3/PM_UCB1CLK/PM_UCA1STE)* 45(P4.4/PM_UCA1TXD/PM_UCA1SIMO)* 46(P4.5/PM_UCA1RXD/PM_UCA1SOMI)* 47(P4.6/PM_NONE)* 48(P4.7/PM_NONE)*

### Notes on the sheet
- C202, C203, C204
  near pin 11,15, 40
- MSP430F5528 COMMUNICATIONS HID-BRIDGE
- Off Sheet Connections

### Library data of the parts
C200 C201 = GRM1555C1H220JA01D: CAP, CERM, 22 pF, 50 V, +/- 5%, C0G/NP0, 0402; Manufacturer: MuRata; Polarized: N; CompType: Capacitor; Value: 22pF; U/M: EA; Cap_F: 0.000000000022; Tolerance_%: 5; Value1: Unknown; VDC_V: 50; Value2: 50V; TaMin_C: -55; TaMax_C: 125; Cap_Case: 0402; AEC Category: Q200
C202-C204 = GRM155R71C104KA88D: as C408 on sheet MCU018A_USB Hub and Pow
C205 = GRM188R61A475MAAJ: CAP, CERM, 4.7 µF, 10 V, +/- 20%, X5R, 0603; Manufacturer: MuRata; Polarized: N; CompType: Capacitor; Value: 4.7uF; U/M: EA; Cap_F: 0.0000047; Tolerance_%: 20; Value1: Unknown; VDC_V: 10; Value2: 10V; TaMin_C: -55; TaMax_C: 85; Cap_Case: 0603; AEC Category: Q200
C206 C207 = GRM155R71C224KA12D: CAP, CERM, 0.22 µF, 16 V, +/- 10%, X7R, 0402; Manufacturer: MuRata; Polarized: N; CompType: Capacitor; Value: 0.22uF; U/M: EA; Cap_F: 0.00000022; Tolerance_%: 10; Value1: Unknown; VDC_V: 16; Value2: 16V; TaMin_C: -55; TaMax_C: 125; Cap_Case: 0402
C208 = GRM155R61C474KE01: CAP, CERM, 0.47 µF, 16 V, +/- 10%, X5R, 0402; Manufacturer: MuRata; Polarized: N; CompType: Capacitor; Value: 0.47uF; U/M: EA; Cap_F: 0.00000047; Tolerance_%: 10; Value1: Unknown; VDC_V: 16; Value2: 16V; TaMin_C: -55; TaMax_C: 85; Cap_Case: 0402
C210 = GRM1555C1H102JA01D: CAP, CERM, 1000 pF, 50 V, +/- 5%, C0G/NP0, 0402; Manufacturer: MuRata; Polarized: N; CompType: Capacitor; Value: 1000pF; U/M: EA; Cap_F: 0.000000001; Tolerance_%: 5; Value1: Unknown; VDC_V: 50; Value2: 50V; TaMin_C: -55; TaMax_C: 125; Cap_Case: 0402
D201 D202 = LTST-C191TGKT: LED, Green, SMD; Manufacturer: Lite-On; Type: InGaN; Vf_V: 3.2; Value2: 3.2V; Io_A: 0.02; Value1: W; U/M: EA
D203 = LTST-C190CKT: LED, Red, SMD; Manufacturer: Lite-On; Vf_V: 2; Value2: 2V; Io_A: 0.02; Tjmax_C: 85; Power_TotalModule: 0.0625; Value1: 0.0625W; U/M: EA
J200 = PBC07SAAN: Header, 2.54 mm, 7x1, Gold, TH; Manufacturer: Sullins Connector Solutions; SymbolCreator: a0411947; Pitch_mm: 2.54; Gender: Male; Shrouded: N; Row_Count: 1; Current_A: 3; Voltage_V: 1800; Cert_UL: Y
Q200 = CSTCR4M00G15L99-R0: Resonator, 4MHz, 39pF SMD; Manufacturer: MuRata; SymbolCreator: a0799721; U/M: EA; TaMin_C: 0; TaMax_C: 70; Frequency Stability: ±0.08 %
R200 R208 = CRCW04022K20JNED: RES, 2.2 k, 5%, 0.063 W, 0402; Manufacturer: Vishay-Dale; CompType: Resistor; Value: 2.2k; Res_ohm: 2200; Value_Code: 2k20; Tolerance_%: 5; Power_W: 0.063; Value2: 0.063W; VDC_V: 50; TempCo: 200 ppm/C; EIA_Code: E24; U/M: EA; AEC Category: Q200
R201 R203 = CRCW040222R0JNED: RES, 22, 5%, 0.063 W, 0402; Manufacturer: Vishay-Dale; CompType: Resistor; Value: 22; Value_Code: 22R0; Tolerance_%: 5; Power_W: 0.063; Value2: 0.063W; VDC_V: 50; TempCo: 200 ppm/C; EIA_Code: E24; U/M: EA; AEC Category: Q200
R202 R204 = CRCW0402390RJNED: RES, 390 ohm, 5%, 0.063W, 0402; Manufacturer: Vishay-Dale; CompType: Resistor; Value_Code: 390R; Tolerance_%: 5; Power_W: 0.063; VDC_V: 50; TempCo: 200 ppm/C; EIA_Code: E24; U/M: EA
R205 = CRCW0402470RJNED: RES, 470, 5%, 0.063 W, 0402; Manufacturer: Vishay-Dale; CompType: Resistor; Value: 470; Value_Code: 470R; Tolerance_%: 5; Power_W: 0.063; Value2: 0.063W; VDC_V: 50; TempCo: 200 ppm/C; EIA_Code: E24; U/M: EA; AEC Category: Q200
R206 = CRCW04021K50JNED: RES, 1.5 k, 5%, 0.063 W, 0402; Manufacturer: Vishay-Dale; CompType: Resistor; Value: 1.5k; Res_ohm: 1500; Value_Code: 1k50; Tolerance_%: 5; Power_W: 0.063; Value2: 0.063W; VDC_V: 50; TempCo: 200 ppm/C; EIA_Code: E24; U/M: EA
R207 = CRCW040210K0JNED: as R418 on sheet MCU018A_USB Hub and Pow
R209 = CRCW040247K0JNED: as R404 on sheet MCU018A_USB Hub and Pow
R210 = CRCW04021M00JNED: RES, 1.0 M, 5%, 0.063 W, 0402; Manufacturer: Vishay-Dale; CompType: Resistor; Value: 1.0Meg; Res_ohm: 1000000; Value_Code: 1M00; Tolerance_%: 5; Power_W: 0.063; Value2: 0.063W; VDC_V: 50; TempCo: 200 ppm/C; EIA_Code: E24; U/M: EA
R211 = CRCW0402100RJNED: RES, 100, 5%, 0.063 W, 0402; Manufacturer: Vishay-Dale; CompType: Resistor; Value: 100; Value_Code: 100R; Tolerance_%: 5; Power_W: 0.063; Value2: 0.063W; VDC_V: 50; TempCo: 200 ppm/C; EIA_Code: E24; U/M: EA
S201 S202 = B3U-1000P: SWITCH TACTILE SPST-NO 0.05A 12V; Manufacturer: Omron Electronic Components; SymbolCreator: a0412235; VDC_V: 12; SwitchFunction: Off-Mom; PositionCount: 1; CurrentRating_mA: 50
U200 = MSP430F5528IRGCR: Mixed Signal MicroController, RGC0064B; Manufacturer: Texas Instruments; Alternate PartNumber: MSP430F5528IRGCT; ADC: 12-bit SAR; ADC Channels: 16; Brown Out Reset: Yes; DMA: 3; Eco-Plan: Green (RoHS & no Sb/Br); Flash(KB): 128; Frequency(MHz): 25; GPIO: 47; Multiplier: 32x32; SRAM(B): 8192; SubFamily: 5 Series; Timers - 16-bit: 4; USB: 1; USCI_A (UART/LIN/IrDA/SPI): 2; SymbolCreator: Altium/a0412235; CompType: IC; U/M: EA
U201 U202 = TPD4E002DRL2: Low-Capacitance Array with + / - 15 kV ESD Protection, 4 Channels, -40 to +85 degC, 5-pin SOT (DRL), Green (RoHS & no Sb/Br); Manufacturer: Texas Instruments; Alternate PartNumber: Equivalent; Breakdown Voltage(Min)(V): 6; IEC 61000-4-2 Air-Gap(+/- kV): 15; IO Capacitance(Typ)(pF): 11; IO Leakage Current(nA): 100; SubFamily: ESD Solution

## Sheet MCU018A_ezFET_lite.SchDoc
size 431 x 279 mm; Date: Not shown in title block; ApprovedBy: Not shown in title block; CheckedBy: Not shown in title block; Author: Not shown in title block; CompanyName: Not shown in title block; Engineer: Not shown in title block; Organization: Not shown in title block; Address1: Not shown in title block; Address2: Not shown in title block; Address3: Not shown in title block; Address4: Not shown in title block; DocumentNumber: 4; Revision: Use project parameter SCH_Rev; SheetNumber: 4; SheetTotal: 6; PageSetup: Record=PageOptions¦CenterHorizontal=True¦CenterVertical=True¦PrintScale=1.00¦XCorrection=1.00¦YCorrection=1.00¦PrintKind=0¦BorderSize=5000000¦LeftOffset=0¦BottomOffset=0¦Orientation=2¦PaperLength=1000¦PaperWidth=1000¦Scale=100¦PaperSource=15¦PrintQuality=600¦MediaType=1¦DitherType=10¦PaperKind=Letter¦PrintScaleMode=1; Monkey Man: me
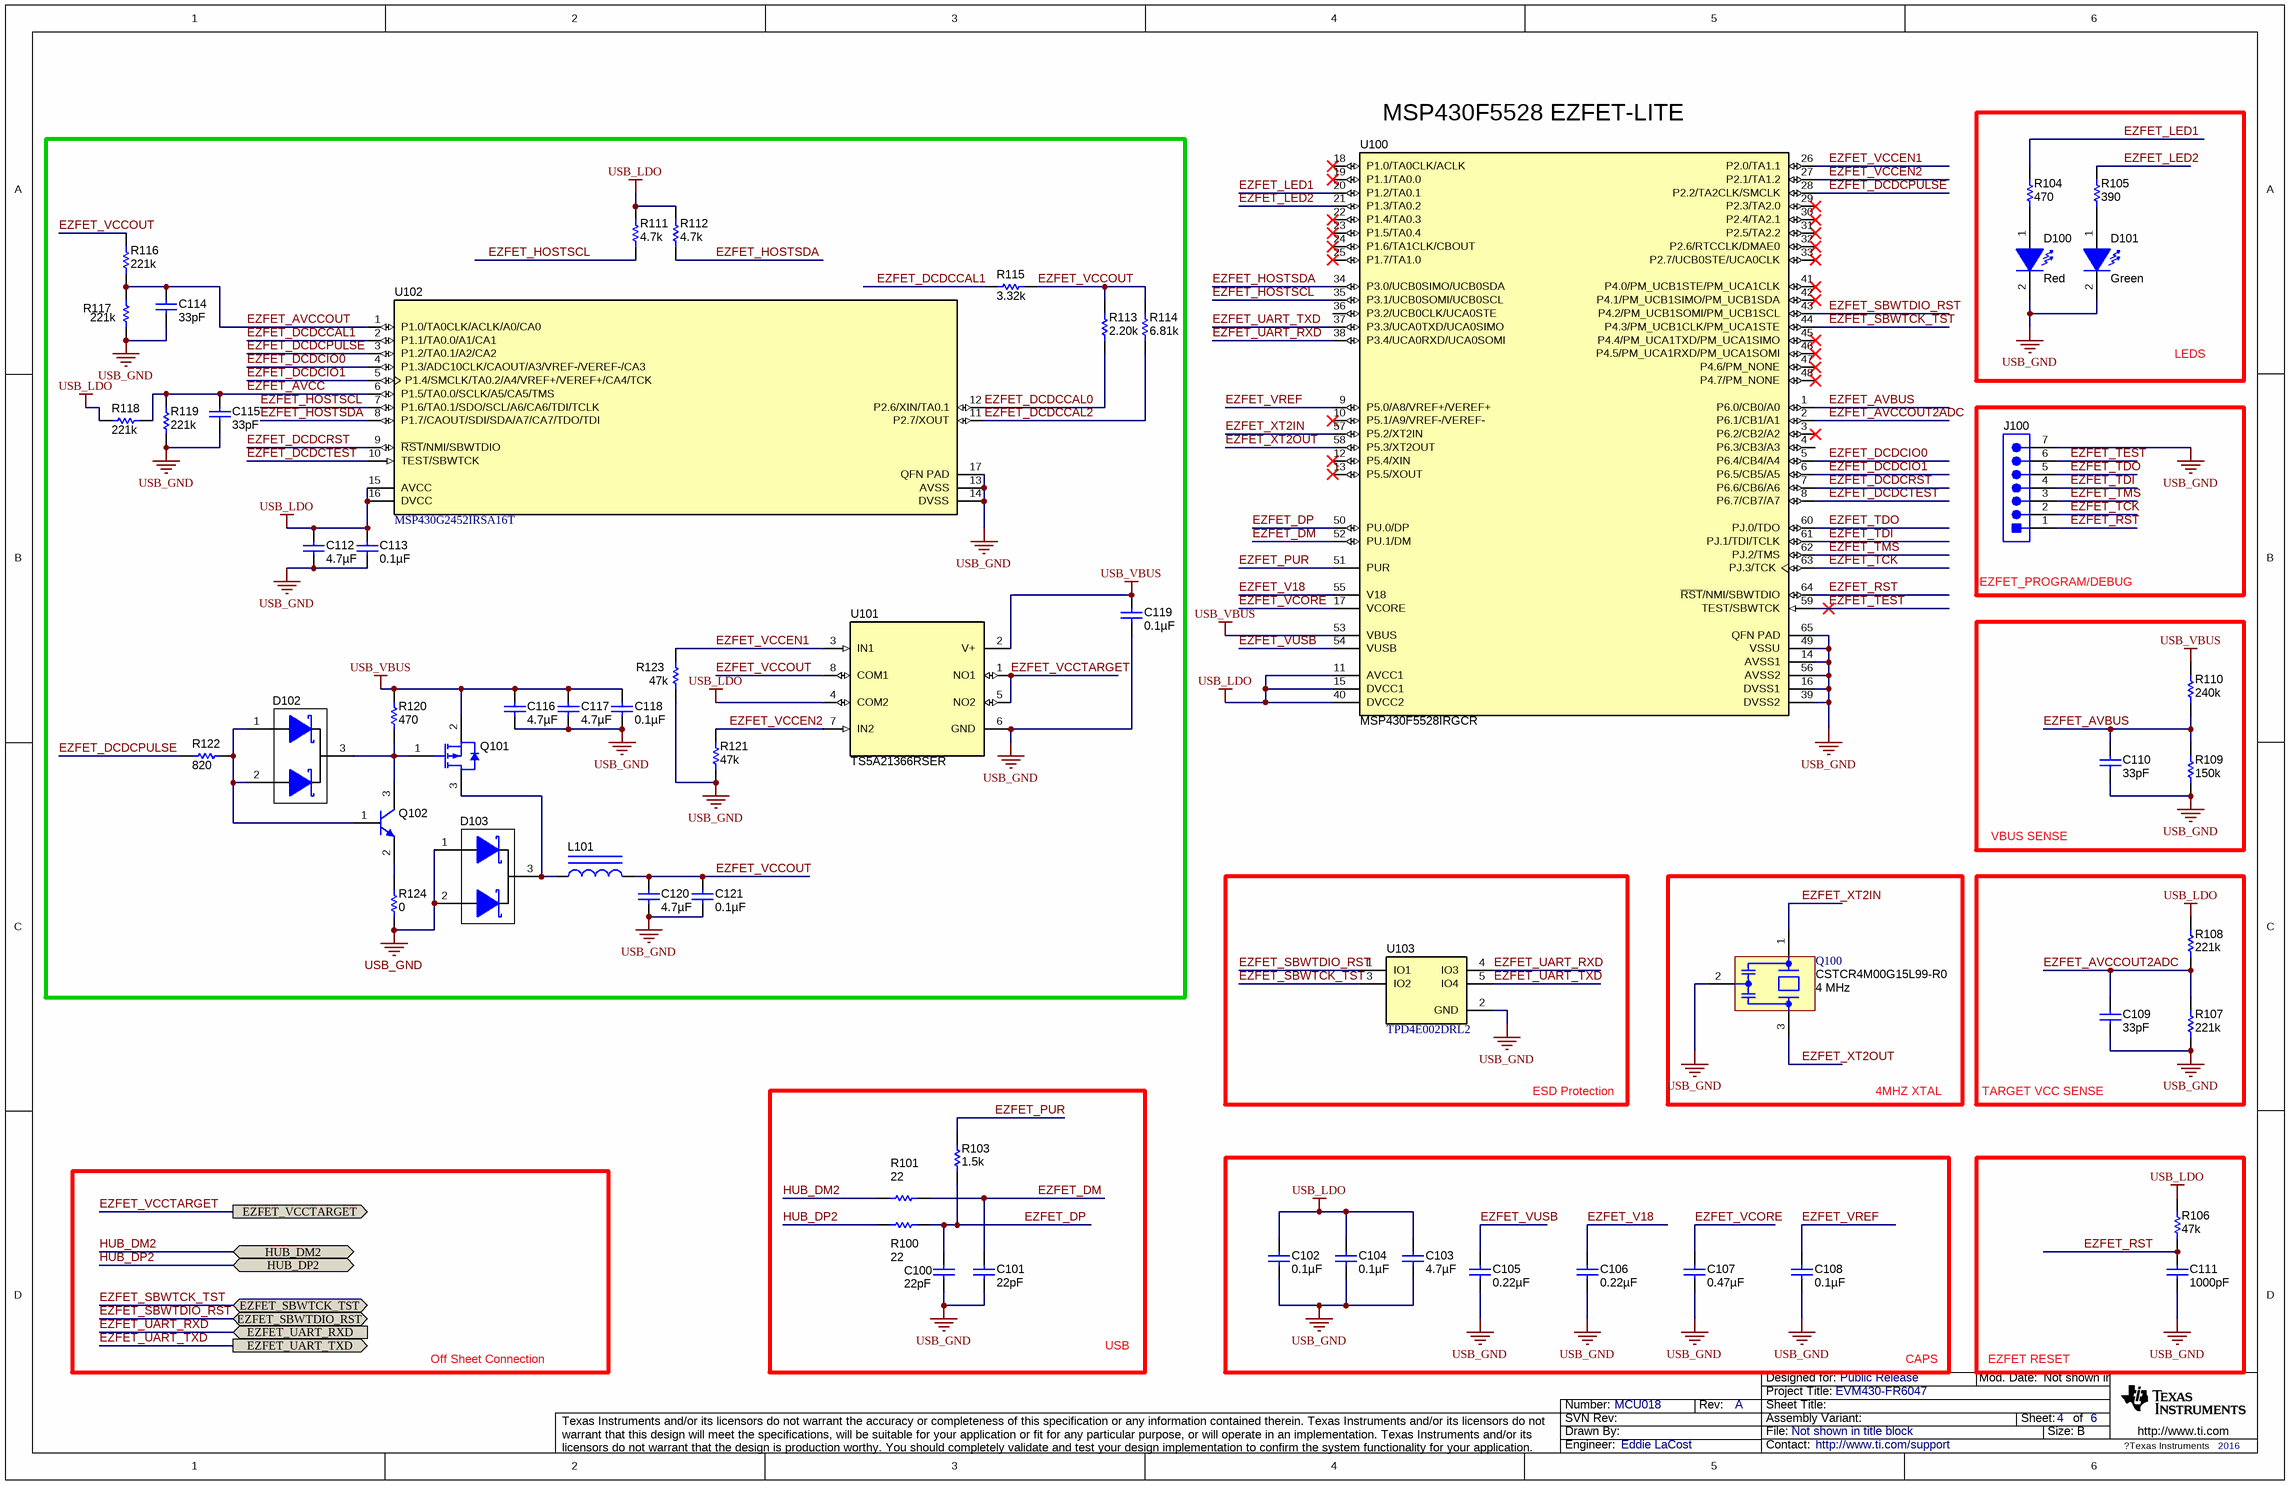
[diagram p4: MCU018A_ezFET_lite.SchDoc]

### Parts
C100  ValueDisplayed: 22pF  [0402S]  (hidden comment: GRM1555C1H220JA01D)
C101  ValueDisplayed: 22pF  [0402S]  (hidden comment: GRM1555C1H220JA01D)
C102  ValueDisplayed: 0.1µF  [0402S]  (hidden comment: GRM155R71C104KA88D)
C103  ValueDisplayed: 4.7µF  [0603S]  (hidden comment: GRM188R61A475MAAJ)
C104  ValueDisplayed: 0.1µF  [0402S]  (hidden comment: GRM155R71C104KA88D)
C105  ValueDisplayed: 0.22µF  [0402S]  (hidden comment: GRM155R71C224KA12D)
C106  ValueDisplayed: 0.22µF  [0402S]  (hidden comment: GRM155R71C224KA12D)
C107  ValueDisplayed: 0.47µF  [0402S]  (hidden comment: GRM155R61C474KE01)
C108  ValueDisplayed: 0.1µF  [0402S]  (hidden comment: GRM155R71C104KA88D)
C109  ValueDisplayed: 33pF  [0402S]  (hidden comment: GRM1555C1H330JA01D)
C110  ValueDisplayed: 33pF  [0402S]  (hidden comment: GRM1555C1H330JA01D)
C111  ValueDisplayed: 1000pF  [0402S]  (hidden comment: GRM1555C1H102JA01D)
C112  ValueDisplayed: 4.7µF  [0603S]  (hidden comment: GRM188R61A475MAAJ)
C113  ValueDisplayed: 0.1µF  [0402S]  (hidden comment: GRM155R71C104KA88D)
C114  ValueDisplayed: 33pF  [0402S]  (hidden comment: GRM1555C1H330JA01D)
C115  ValueDisplayed: 33pF  [0402S]  (hidden comment: GRM1555C1H330JA01D)
C116  ValueDisplayed: 4.7µF  [0603S]  (hidden comment: GRM188R61A475MAAJ)
C117  ValueDisplayed: 4.7µF  [0603S]  (hidden comment: GRM188R61A475MAAJ)
C118  ValueDisplayed: 0.1µF  [0402S]  (hidden comment: GRM155R71C104KA88D)
C119  ValueDisplayed: 0.1µF  [0402S]  (hidden comment: GRM155R71C104KA88D)
C120  ValueDisplayed: 4.7µF  [0603S]  (hidden comment: GRM188R61A475MAAJ)
C121  ValueDisplayed: 0.1µF  [0402S]  (hidden comment: GRM155R71C104KA88D)
D100  value Red  [LED_LTST-C190_Red]  (hidden comment: LTST-C190CKT)
D101  value Green  [LTST-C191_Green]  (hidden comment: LTST-C191TGKT)
D102  BAS40-05-7-F  [SOT-23]  (value not drawn)
D103  BAS40-05-7-F  [SOT-23]  (value not drawn)
J100  PBC07SAAN  [Sullins_xxC07SAAN]  (value not drawn)
L101  CIG21L2R2MNE  [0805]  (value not drawn)
Q100  CSTCR4M00G15L99-R0  Frequency: 4 MHz  [Murata_CSTCR]
Q101  DMG1013UW  [SOT-323]  (value not drawn)
Q102  BC850CLT1G  [SOT-23]  (value not drawn)
R100  ValueDisplayed: 22  [0402S]  (hidden comment: CRCW040222R0JNED)
R101  ValueDisplayed: 22  [0402S]  (hidden comment: CRCW040222R0JNED)
R103  ValueDisplayed: 1.5k  [0402S]  (hidden comment: CRCW04021K50JNED)
R104  value 470  [0402S]  (hidden comment: CRCW0402470RJNED)
R105  value 390  [0402S]  (hidden comment: CRCW0402390RJNED)
R106  value 47k  [0402S]  (hidden comment: CRCW040247K0JNED)
R107  ValueDisplayed: 221k  [0402S]  (hidden comment: CRCW0402221KFKED)
R108  ValueDisplayed: 221k  [0402S]  (hidden comment: CRCW0402221KFKED)
R109  ValueDisplayed: 150k  [0402S]  (hidden comment: CRCW0402150KFKED)
R110  ValueDisplayed: 240k  [0402S]  (hidden comment: CRCW0402240KFKED)
R111  ValueDisplayed: 4.7k  [0402S]  (hidden comment: CRCW04024K70JNED)
R112  ValueDisplayed: 4.7k  [0402S]  (hidden comment: CRCW04024K70JNED)
R113  ValueDisplayed: 2.20k  [0402S]  (hidden comment: CRCW04022K20FKED)
R114  ValueDisplayed: 6.81k  [0402S]  (hidden comment: CRCW04026K81FKED)
R115  ValueDisplayed: 3.32k  [0402S]  (hidden comment: CRCW04023K32FKED)
R116  ValueDisplayed: 221k  [0402S]  (hidden comment: CRCW0402221KFKED)
R117  ValueDisplayed: 221k  [0402S]  (hidden comment: CRCW0402221KFKED)
R118  ValueDisplayed: 221k  [0402S]  (hidden comment: CRCW0402221KFKED)
R119  ValueDisplayed: 221k  [0402S]  (hidden comment: CRCW0402221KFKED)
R120  ValueDisplayed: 470  [0402S]  (hidden comment: CRCW0402470RJNED)
R121  ValueDisplayed: 47k  [0402S]  (hidden comment: CRCW040247K0JNED)
R122  ValueDisplayed: 820  [0402S]  (hidden comment: CRCW0402820RJNED)
R123  ValueDisplayed: 47k  [0402S]  (hidden comment: CRCW040247K0JNED)
R124  ValueDisplayed: 0  [0402S]  (hidden comment: CRCW04020000Z0ED)
U100  MSP430F5528IRGCR  [RGC0064B]
U101  TS5A21366RSER  [RSE0008A]
U102  MSP430G2452IRSA16T  [RSA0016B]
U103  TPD4E002DRL2  [DRL0005A]

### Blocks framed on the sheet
LEDS: D100 D101 R104 R105
EZFET_PROGRAM/DEBUG: J100
VBUS SENSE: C110 R109 R110
ESD Protection: U103
4MHZ XTAL: Q100
TARGET VCC SENSE: C109 R107 R108
USB: C100 C101 R100 R101 R103
CAPS: C102-C108
EZFET RESET: C111 R106

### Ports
EZFET_SBWTCK_TST (bidir), EZFET_SBWTDIO_RST (bidir), EZFET_UART_RXD (in), EZFET_UART_TXD (out), EZFET_VCCTARGET, HUB_DM2 (bidir), HUB_DP2 (bidir)

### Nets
USB_GND: C100.2 C101.2 C102.2 C103.2 C104.2 C105.2 C106.2 C107.2 C108.2 C109.2 C110.2 C111.2 C112.2 C113.2 C114.2 C115.2 C116.2 C117.2 C118.2 C119.2 C120.2 C121.2 D100.2(K) D101.2(K) D103.1(A) D103.2(K) J100.7 Q100.2(GND) R107.1 R109.1 R117.1 R119.1 R121.1 R123.1 R124.2 U100.14(AVSS1) U100.16(DVSS1) U100.39(DVSS2) U100.49(VSSU) U100.56(AVSS2) U100.65(QFN_PAD) U101.6(GND) U102.13(AVSS) U102.14(DVSS) U102.17(QFN_PAD) U103.2(GND)
USB_LDO: C102.1 C103.1 C104.1 C112.1 C113.1 R106.2 R108.2 R111.1 R112.1 R118.1 U100.11(AVCC1) U100.15(DVCC1) U100.40(DVCC2) U101.4(COM2) U102.15(AVCC) U102.16(DVCC)
USB_VBUS: C116.1 C117.1 C118.1 C119.1 Q101.2(S) R110.2 R120.1 U100.53(VBUS) U101.2(V+)
EZFET_AVBUS: C110.1 R109.2 R110.1 U100.1(P6.0/CB0/A0)
EZFET_AVCC: C115.1 R118.2 R119.2 U102.6(P1.5/TA0.0/SCLK/A5/CA5/TMS)
EZFET_AVCCOUT: C114.1 R116.1 R117.2 U102.1(P1.0/TA0CLK/ACLK/A0/CA0)
EZFET_AVCCOUT2ADC: C109.1 R107.2 R108.1 U100.2(P6.1/CB1/A1)
EZFET_DCDCCAL0: R113.1 U102.12(P2.6/XIN/TA0.1)
EZFET_DCDCCAL1: R115.2 U102.2(P1.1/TA0.0/A1/CA1)
EZFET_DCDCCAL2: R114.1 U102.11(P2.7/XOUT)
EZFET_DCDCIO0: U100.5(P6.4/CB4/A4) U102.4(P1.3/ADC10CLK/CAOUT/A3/VREF-/VEREF-/CA3)
EZFET_DCDCIO1: U100.6(P6.5/CB5/A5) U102.5(P1.4/SMCLK/TA0.2/A4/VREF+/VEREF+/CA4/TCK)
EZFET_DCDCPULSE: R122.2 U100.28(P2.2/TA2CLK/SMCLK) U102.3(P1.2/TA0.1/A2/CA2)
EZFET_DCDCRST: U100.7(P6.6/CB6/A6) U102.9(~{RST}/NMI/SBWTDIO)
EZFET_DCDCTEST: U100.8(P6.7/CB7/A7) U102.10(TEST/SBWTCK)
EZFET_DM: C101.1 R101.2 U100.52(PU.1/DM)
EZFET_DP: C100.1 R100.2 R103.2 U100.50(PU.0/DP)
EZFET_HOSTSCL: R111.2 U100.35(P3.1/UCB0SOMI/UCB0SCL) U102.7(P1.6/TA0.1/SDO/SCL/A6/CA6/TDI/TCLK)
EZFET_HOSTSDA: R112.2 U100.34(P3.0/UCB0SIMO/UCB0SDA) U102.8(P1.7/CAOUT/SDI/SDA/A7/CA7/TDO/TDI)
EZFET_LED1: R104.2 U100.20(P1.2/TA0.1)
EZFET_LED2: R105.2 U100.21(P1.3/TA0.2)
EZFET_PUR: R103.1 U100.51(PUR)
EZFET_RST: C111.1 J100.1 R106.1 U100.64(~{RST}/NMI/SBWTDIO)
EZFET_SBWTCK_TST: U100.44(P4.3/PM_UCB1CLK/PM_UCA1STE) U103.3(IO2) ; port EZFET_SBWTCK_TST
EZFET_SBWTDIO_RST: U100.43(P4.2/PM_UCB1SOMI/PM_UCB1SCL) U103.1(IO1) ; port EZFET_SBWTDIO_RST
EZFET_TCK: J100.2 U100.63(PJ.3/TCK)
EZFET_TDI: J100.4 U100.61(PJ.1/TDI/TCLK)
EZFET_TDO: J100.5 U100.60(PJ.0/TDO)
EZFET_TEST: J100.6 U100.59(TEST/SBWTCK)
EZFET_TMS: J100.3 U100.62(PJ.2/TMS)
EZFET_UART_RXD: U100.38(P3.4/UCA0RXD/UCA0SOMI) U103.4(IO3) ; port EZFET_UART_RXD
EZFET_UART_TXD: U100.37(P3.3/UCA0TXD/UCA0SIMO) U103.5(IO4) ; port EZFET_UART_TXD
EZFET_V18: C106.1 U100.55(V18)
EZFET_VCCEN1: R123.2 U100.26(P2.0/TA1.1) U101.3(IN1)
EZFET_VCCEN2: R121.2 U100.27(P2.1/TA1.2) U101.7(IN2)
EZFET_VCCOUT: C120.1 C121.1 L101.2 R113.2 R114.2 R115.1 R116.2 U101.8(COM1)
EZFET_VCCTARGET: U101.1(NO1) U101.5(NO2) ; port EZFET_VCCTARGET
EZFET_VCORE: C107.1 U100.17(VCORE)
EZFET_VREF: C108.1 U100.9(P5.0/A8/VREF+/VEREF+)
EZFET_VUSB: C105.1 U100.54(VUSB)
EZFET_XT2IN: Q100.1(In) U100.57(P5.2/XT2IN)
EZFET_XT2OUT: Q100.3(Out) U100.58(P5.3/XT2OUT)
HUB_DM2: R101.1 ; port HUB_DM2
HUB_DP2: R100.1 ; port HUB_DP2
NetD100_1: D100.1(A) R104.1
NetD101_1: D101.1(A) R105.1
NetD102_1: D102.1(A) D102.2(K) Q102.1(B) R122.1
NetD102_3: D102.3(A) Q101.1(G) Q102.3(C) R120.2
NetD103_3: D103.3(A) L101.1 Q101.3(D)
NetQ102_2: Q102.2(E) R124.1

Not connected (* = marked no-connect by the designer): U100 3(P6.2/CB2/A2)* 4(P6.3/CB3/A3) 10(P5.1/A9/VREF-/VEREF-)* 12(P5.4/XIN)* 13(P5.5/XOUT)* 18(P1.0/TA0CLK/ACLK)* 19(P1.1/TA0.0)* 22(P1.4/TA0.3)* 23(P1.5/TA0.4)* 24(P1.6/TA1CLK/CBOUT)* 25(P1.7/TA1.0)* 29(P2.3/TA2.0)* 30(P2.4/TA2.1)* 31(P2.5/TA2.2)* 32(P2.6/RTCCLK/DMAE0)* 33(P2.7/UCB0STE/UCA0CLK)* 36(P3.2/UCB0CLK/UCA0STE) 41(P4.0/PM_UCB1STE/PM_UCA1CLK)* 42(P4.1/PM_UCB1SIMO/PM_UCB1SDA)* 45(P4.4/PM_UCA1TXD/PM_UCA1SIMO)* 46(P4.5/PM_UCA1RXD/PM_UCA1SOMI)* 47(P4.6/PM_NONE)* 48(P4.7/PM_NONE)*

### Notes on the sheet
- (near U100) MSP430F5528 EZFET-LITE
- Off Sheet Connection

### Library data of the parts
C100 C101 = GRM1555C1H220JA01D: as C200 on sheet MCU018A_Comm Interface
C102 C104 C108 C113 C118 C119 C121 = GRM155R71C104KA88D: as C408 on sheet MCU018A_USB Hub and Pow
C103 C112 C116 C117 C120 = GRM188R61A475MAAJ: as C205 on sheet MCU018A_Comm Interface
C105 C106 = GRM155R71C224KA12D: as C206 on sheet MCU018A_Comm Interface
C107 = GRM155R61C474KE01: as C208 on sheet MCU018A_Comm Interface
C109 C110 C114 C115 = GRM1555C1H330JA01D: CAP, CERM, 33 pF, 50 V, +/-5%, C0G/NP0, 0402; Manufacturer: MuRata; Polarized: N; CompType: Capacitor; Value: 33pF; U/M: EA; Cap_F: 0.000000000033; Tolerance_%: 5; Value1: Unknown; VDC_V: 50; Value2: 50V; TaMin_C: -55; TaMax_C: 125; Cap_Case: 0402
C111 = GRM1555C1H102JA01D: as C210 on sheet MCU018A_Comm Interface
D100 = LTST-C190CKT: as D203 on sheet MCU018A_Comm Interface
D101 = LTST-C191TGKT: as D201 on sheet MCU018A_Comm Interface
D102 D103 = BAS40-05-7-F: Diode, Schottky, 40V, 0.2A, SOT-23; Manufacturer: Diodes Inc.; SymbolCreator: a0412235; U/M: EA; Vf_V: 0.9; Value2: 0.9V; Io_A: 0.2; Vr_V: 40
J100 = PBC07SAAN: as J200 on sheet MCU018A_Comm Interface
L101 = CIG21L2R2MNE: Inductor, Shielded, Composite, 2.2uH, 0.95A, 0.16 ohm, SMD; Manufacturer: Samsung; Ind_H: 2.2E-6; ValueDisplayed: 2.2µH; Imax_A: 0.95; Irms: 0.95A @ 40C rise; DCR_ohm: 0.16
Q100 = CSTCR4M00G15L99-R0: as Q200 on sheet MCU018A_Comm Interface
Q101 = BSS84W-7-F: MOSFET, P-CH, -50V, -0.13A, SOT-323; Manufacturer: Diodes Inc.; Alternate Manufacturer: None; U/M: EA; ChType: P; VdsMax_V: -50; Value1: 10 ohm; Rdson45_Ohm: 10; Value2: ? nC; Vgs_V: -20; IdsMax_A: -0.13
Q102 = BC850CLT1G, ON Semiconductor: Transistor, NPN, 45V, 0.1A, SOT-23; CompType: BJT; PNP: 0; NPN: 1; Vceo_V: 45; Vcesat1_V: 0.7; Value: 0.7V; IcRated_A: 0.1; HfeMax: 800; TaMin_C: -55; TaMax_C: 150; U/M: EA
R100 R101 = CRCW040222R0JNED: RES, 22, 5%, 0.063 W, 0402; Manufacturer: Vishay-Dale; CompType: Resistor; Value_Code: 22R0; Tolerance_%: 5; Power_W: 0.063; Value2: 0.063W; VDC_V: 50; TempCo: 200 ppm/C; EIA_Code: E24; U/M: EA; Value: 22; AEC Category: Q200
R103 = CRCW04021K50JNED: RES, 1.5 k, 5%, 0.063 W, 0402; Manufacturer: Vishay-Dale; CompType: Resistor; Res_ohm: 1500; Value_Code: 1k50; Tolerance_%: 5; Power_W: 0.063; Value2: 0.063W; VDC_V: 50; TempCo: 200 ppm/C; EIA_Code: E24; U/M: EA; Value: 1.5k
R104 = CRCW0402470RJNED: RES, 470, 5%, 0.063 W, 0402; Manufacturer: Vishay-Dale; CompType: Resistor; Value_Code: 470R; Tolerance_%: 5; Power_W: 0.063; Value2: 0.063W; VDC_V: 50; TempCo: 200 ppm/C; EIA_Code: E24; U/M: EA
R105 = CRCW0402390RJNED: as R202 on sheet MCU018A_Comm Interface
R106 = CRCW040247K0JNED: as R404 on sheet MCU018A_USB Hub and Pow
R107 R108 R116-R119 = CRCW0402221KFKED: RES, 221 k, 1%, 0.063 W, 0402; Manufacturer: Vishay-Dale; CompType: Resistor; Res_ohm: 221000; Tolerance_%: 1; Power_W: 0.063; Value2: 0.063W; VDC_V: 50; TempCo: 100 ppm/C; EIA_Code: E96; U/M: EA; Value: 221k; AEC Category: Q200
R109 = CRCW0402150KFKED: RES, 150 k, 1%, 0.063 W, 0402; Manufacturer: Vishay-Dale; CompType: Resistor; Res_ohm: 150000; Tolerance_%: 1; Power_W: 0.063; Value2: 0.063W; VDC_V: 50; TempCo: 100 ppm/C; EIA_Code: E96; U/M: EA; Value: 150k; AEC Category: Q200
R110 = CRCW0402240KFKED: RES, 240 k, 1%, 0.063 W, 0402; Manufacturer: Vishay-Dale; CompType: Resistor; Res_ohm: 240000; Tolerance_%: 1; Power_W: 0.063; Value2: 0.063W; VDC_V: 50; TempCo: 100 ppm/C; U/M: EA; Value: 240k; AEC Category: Q200
R111 R112 = CRCW04024K70JNED: RES, 4.7 k, 5%, 0.063 W, 0402; Manufacturer: Vishay-Dale; CompType: Resistor; Res_ohm: 4700; Value_Code: 4k70; Tolerance_%: 5; Power_W: 0.063; Value2: 0.063W; VDC_V: 50; TempCo: 200 ppm/C; EIA_Code: E24; U/M: EA; Value: 4.7k
R113 = CRCW04022K20FKED: RES, 2.20 k, 1%, 0.063 W, 0402; Manufacturer: Vishay-Dale; CompType: Resistor; Res_ohm: 2200; Value_Code: 2k20; Tolerance_%: 1; Power_W: 0.063; Value2: 0.063W; TempCo: 100 ppm/C; U/M: EA; Value: 2.20k; AEC Category: Q200
R114 = CRCW04026K81FKED: RES, 6.81 k, 1%, 0.063 W, 0402; Manufacturer: Vishay-Dale; CompType: Resistor; Res_ohm: 6810; Value_Code: 6k81; Tolerance_%: 1; Power_W: 0.063; Value2: 0.063W; VDC_V: 50; TempCo: 100 ppm/C; EIA_Code: E96; U/M: EA; Value: 6.81k; AEC Category: Q200
R115 = CRCW04023K32FKED: RES, 3.32 k, 1%, 0.063 W, 0402; Manufacturer: Vishay-Dale; CompType: Resistor; Res_ohm: 3320; Value_Code: 3k32; Tolerance_%: 1; Power_W: 0.063; Value2: 0.063W; VDC_V: 50; TempCo: 100 ppm/C; EIA_Code: E96; U/M: EA; Value: 3.32k; AEC Category: Q200
R120 = CRCW0402470RJNED: RES, 470, 5%, 0.063 W, 0402; Manufacturer: Vishay-Dale; CompType: Resistor; Value_Code: 470R; Tolerance_%: 5; Power_W: 0.063; Value2: 0.063W; VDC_V: 50; TempCo: 200 ppm/C; EIA_Code: E24; U/M: EA; Value: 470
R121 R123 = CRCW040247K0JNED: RES, 47 k, 5%, 0.063 W, 0402; Manufacturer: Vishay-Dale; CompType: Resistor; Res_ohm: 47000; Value_Code: 47k0; Tolerance_%: 5; Power_W: 0.063; Value2: 0.063W; VDC_V: 50; TempCo: 200 ppm/C; EIA_Code: E24; U/M: EA; Value: 47k
R122 = CRCW0402820RJNED: RES, 820, 5%, 0.063 W, 0402; Manufacturer: Vishay-Dale; CompType: Resistor; Value_Code: 820R; Tolerance_%: 5; Power_W: 0.063; Value2: 0.063W; VDC_V: 50; TempCo: 200 ppm/C; EIA_Code: E24; U/M: EA; Value: 820
R124 = CRCW04020000Z0ED: RES, 0, 5%, 0.063 W, 0402; Manufacturer: Vishay-Dale; CompType: Resistor; Value_Code: 0000; Tolerance_%: 5; Power_W: 0.063; Value2: 0.063W; VDC_V: 50; TempCo: 200 ppm/C; EIA_Code: E24; U/M: EA; Value: 0
U100 = MSP430F5528IRGCR: as U200 on sheet MCU018A_Comm Interface
U101 = CMP-0074338-2: 0.75-Ohm DUAL SPST ANALOG SWITCH WITH 1.8-V COMPATIBLE INPUT LOGIC, RSE0008A (UQFN-8); Manufacturer: Texas Instruments; SizeZ_mm: 0.6; SizeX_mm: 1.5; SizeArea_mm2: 2.25; CompType: IC; U/M: EA; SizeAreaWB_mm2: 6.25
U102 = CMP-0039612-1: 16 MHz Mixed Signal Microcontroller with 8 KB Flash, 256 B SRAM and 16 GPIOs, 16-pin QFN (RSA), Green (RoHS & no Sb/Br); Manufacturer: Texas Instruments; GPIO: 16; Cap touch I/O: Yes; SRAM(B): 256; ADC: 10-bit SAR; Timers - 16-bit: 1; USI: "(I2C/SPI)","1"; SubFamily: Value Line; ADC Channels: 8
U103 = TPD4E002DRL2: as U201 on sheet MCU018A_Comm Interface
